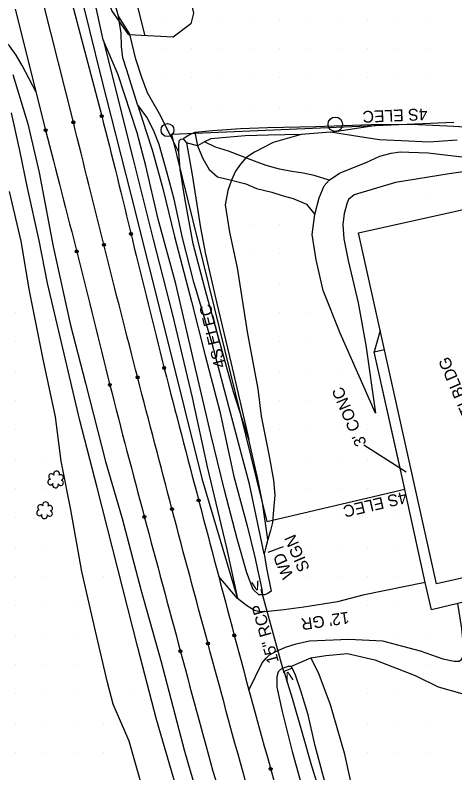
# Model space of a CAD drawing. Extents: x 1548934 to 1561348, y 809680 to 824075.
# Drawn here: x 1551639.7 to 1551789.7, y 811053 to 811311.4 of the extents above; entities that cross this region are included whole.
import ezdxf

# ---------------------------------------------------------------- set-up
doc = ezdxf.new("R2010")
doc.units = 0
for name, color, linetype in [('Default', 7, 'Continuous'), ('E_NCDOT_Vertical_Profile_Ground_Line', 7, 'Continuous'), ('Exist Building', 7, 'Continuous'), ('Exist Building Foundations Text', 7, 'Continuous'), ('Exist DTM QL2 LIDAR Elevation Point', 7, 'Continuous'), ('Exist Other Culture Area Outline', 7, 'Continuous'), ('Exist Other Culture Area Outline Leader', 7, 'Continuous'), ('Exist Other Culture Area Outline Text', 7, 'Continuous'), ('Exist Other Culture Fence Line Text', 7, 'Continuous'), ('Exist Other Culture Sign', 7, 'Continuous'), ('Exist Other Culture Sign Text', 7, 'Continuous'), ('Exist Roads Soil', 7, 'Continuous'), ('Exist Roads Soil Text', 7, 'Continuous'), ('Exist Structure Minor Culvert Topo', 7, 'Continuous'), ('Exist Structure Minor Culvert Topo Terminator', 7, 'Continuous'), ('Exist Structure Minor Pipes RCP 15 Inch Text', 7, 'Continuous'), ('Exist Utilities Other Pole CELL', 7, 'Continuous'), ('Exist Vegetation Shrub CELL', 7, 'Continuous'), ('Exist Vegetation Woods Line', 7, 'Continuous'), ('P_NCDOT_Horizontal_Alignment_Tick_Large', 7, 'Continuous'), ('P_NCDOT_Vertical_Profile_Grade_Minor_Road', 7, 'Continuous'), ('P_RDY_Dimension_Text', 7, 'Continuous'), ('P_RDY_Paved_Shoulder', 7, 'Continuous'), ('PH Exist DTM Breakline', 7, 'Continuous')]:
    doc.layers.add(name, color=color, linetype=linetype)

# ---------------------------------------------------------------- blocks, each defined once
blk = doc.blocks.new('SurveyPointCell')
at = {"layer": 'Default'}
for p, q in [((-0.5, 0), (0.5, 0)), ((0, -0.5), (0, 0.5))]:
    blk.add_line(p, q, dxfattribs=at)
blk.add_circle((0, 0), 0.5, dxfattribs=at)

msp = doc.modelspace()

# ---------------------------------------------------------------- linework, layer by layer
at = {"layer": 'E_NCDOT_Vertical_Profile_Ground_Line'}
for p, q in [((1551658.19, 811318.94), (1551669.23, 811277)), ((1551639.73, 811313.5), (1551650.09, 811272.18))]:
    msp.add_line(p, q, dxfattribs=at)
for points in [[(1551669.23, 811277), (1551672.74, 811263.65), (1551679.61, 811234.97), (1551690.37, 811191.22), (1551702.41, 811145.66), (1551714.33, 811100.03), (1551727, 811053.45), (1551740.47, 811006.5), (1551755.13, 810959.34), (1551769.1, 810915.85), (1551778.93, 810888.33), (1551783.17, 810876.09)], [(1551650.09, 811272.18), (1551653.54, 811258.38), (1551661.25, 811229.55), (1551671.78, 811185.41), (1551683.85, 811140.03), (1551696.07, 811094.56), (1551708.62, 811047.91), (1551722.36, 811000.57), (1551736.98, 810952.93), (1551751.55, 810908.96), (1551760.88, 810880.92), (1551765.29, 810868.44)]]:
    msp.add_open_spline(points, degree=3, dxfattribs=at)
at = {"layer": 'Exist Building'}
msp.add_lwpolyline([(1551783.41, 811117.5), (1551756.83, 811237.21), (1551806.41, 811248.22), (1551832.98, 811128.51)], close=True, dxfattribs=at)
at = {"layer": 'Exist DTM QL2 LIDAR Elevation Point'}
for p, q in [((1551689.99, 811310.04), (1551689.99, 811310.04)), ((1551699.99, 811310.04), (1551699.99, 811310.04)), ((1551710, 811310.04), (1551710, 811310.04)), ((1551720, 811310.04), (1551720, 811310.04)), ((1551730, 811310.04), (1551730, 811310.04)), ((1551740, 811310.04), (1551740, 811310.04)), ((1551750, 811310.04), (1551750, 811310.04)), ((1551760, 811310.04), (1551760, 811310.04)), ((1551770, 811310.04), (1551770, 811310.04)), ((1551780, 811310.04), (1551780, 811310.04)), ((1551689.99, 811300.03), (1551689.99, 811300.03)), ((1551699.99, 811300.03), (1551699.99, 811300.03)), ((1551710, 811300.03), (1551710, 811300.03)), ((1551720, 811300.03), (1551720, 811300.03)), ((1551730, 811300.03), (1551730, 811300.03)), ((1551740, 811300.03), (1551740, 811300.03)), ((1551750, 811300.03), (1551750, 811300.03)), ((1551760, 811300.03), (1551760, 811300.03)), ((1551770, 811300.03), (1551770, 811300.03)), ((1551780, 811300.03), (1551780, 811300.03)), ((1551689.99, 811290.03), (1551689.99, 811290.03)), ((1551699.99, 811290.03), (1551699.99, 811290.03)), ((1551710, 811290.03), (1551710, 811290.03)), ((1551720, 811290.03), (1551720, 811290.03)), ((1551730, 811290.03), (1551730, 811290.03)), ((1551740, 811290.03), (1551740, 811290.03)), ((1551750, 811290.03), (1551750, 811290.03)), ((1551760, 811290.03), (1551760, 811290.03)), ((1551770, 811290.03), (1551770, 811290.03)), ((1551780, 811290.03), (1551780, 811290.03)), ((1551699.99, 811280.03), (1551699.99, 811280.03)), ((1551710, 811280.03), (1551710, 811280.03)), ((1551720, 811280.03), (1551720, 811280.03)), ((1551730, 811280.03), (1551730, 811280.03)), ((1551740, 811280.03), (1551740, 811280.03)), ((1551750, 811280.03), (1551750, 811280.03)), ((1551760, 811280.03), (1551760, 811280.03)), ((1551770, 811280.03), (1551770, 811280.03)), ((1551780, 811280.03), (1551780, 811280.03)), ((1551780, 811250.03), (1551780, 811250.03)), ((1551720, 811240.03), (1551720, 811240.03)), ((1551730, 811240.03), (1551730, 811240.03)), ((1551760, 811240.03), (1551760, 811240.03)), ((1551720, 811230.03), (1551720, 811230.03)), ((1551730, 811230.03), (1551730, 811230.03)), ((1551730, 811220.03), (1551730, 811220.03)), ((1551639.99, 811210.03), (1551639.99, 811210.03)), ((1551730, 811210.03), (1551730, 811210.03)), ((1551740, 811210.03), (1551740, 811210.03)), ((1551639.99, 811200.03), (1551639.99, 811200.03)), ((1551730, 811200.03), (1551730, 811200.03)), ((1551740, 811200.03), (1551740, 811200.03)), ((1551639.99, 811190.03), (1551639.99, 811190.03)), ((1551730, 811190.03), (1551730, 811190.03)), ((1551740, 811190.03), (1551740, 811190.03)), ((1551750, 811190.03), (1551750, 811190.03)), ((1551639.99, 811180.03), (1551639.99, 811180.03)), ((1551730, 811180.03), (1551730, 811180.03)), ((1551740, 811180.03), (1551740, 811180.03)), ((1551750, 811180.03), (1551750, 811180.03)), ((1551639.99, 811170.02), (1551639.99, 811170.02)), ((1551730, 811170.02), (1551730, 811170.02)), ((1551740, 811170.02), (1551740, 811170.02)), ((1551750, 811170.02), (1551750, 811170.02)), ((1551760, 811170.02), (1551760, 811170.02)), ((1551639.99, 811160.02), (1551639.99, 811160.02)), ((1551649.99, 811160.02), (1551649.99, 811160.02)), ((1551740, 811160.02), (1551740, 811160.02)), ((1551750, 811160.02), (1551750, 811160.02)), ((1551760, 811160.02), (1551760, 811160.02)), ((1551639.99, 811150.02), (1551639.99, 811150.02)), ((1551649.99, 811150.02), (1551649.99, 811150.02)), ((1551740, 811150.02), (1551740, 811150.02)), ((1551750, 811150.02), (1551750, 811150.02)), ((1551760, 811150.02), (1551760, 811150.02)), ((1551639.99, 811140.02), (1551639.99, 811140.02)), ((1551649.99, 811140.02), (1551649.99, 811140.02)), ((1551740, 811140.02), (1551740, 811140.02)), ((1551750, 811140.02), (1551750, 811140.02)), ((1551760, 811140.02), (1551760, 811140.02)), ((1551770, 811140.02), (1551770, 811140.02)), ((1551639.99, 811130.02), (1551639.99, 811130.02)), ((1551649.99, 811130.02), (1551649.99, 811130.02)), ((1551740, 811130.02), (1551740, 811130.02)), ((1551750, 811130.02), (1551750, 811130.02)), ((1551760, 811130.02), (1551760, 811130.02)), ((1551770, 811130.02), (1551770, 811130.02)), ((1551639.99, 811120.02), (1551639.99, 811120.02)), ((1551649.99, 811120.02), (1551649.99, 811120.02)), ((1551669.99, 811120.02), (1551669.99, 811120.02)), ((1551740, 811120.02), (1551740, 811120.02)), ((1551750, 811120.02), (1551750, 811120.02)), ((1551760, 811120.02), (1551760, 811120.02)), ((1551770, 811120.02), (1551770, 811120.02)), ((1551639.99, 811110.02), (1551639.99, 811110.02)), ((1551649.99, 811110.02), (1551649.99, 811110.02)), ((1551659.99, 811110.02), (1551659.99, 811110.02)), ((1551760, 811110.02), (1551760, 811110.02)), ((1551770, 811110.02), (1551770, 811110.02)), ((1551639.99, 811100.02), (1551639.99, 811100.02)), ((1551649.99, 811100.02), (1551649.99, 811100.02)), ((1551659.99, 811100.02), (1551659.99, 811100.02)), ((1551720, 811100.02), (1551720, 811100.02)), ((1551730, 811100.02), (1551730, 811100.02)), ((1551770, 811100.02), (1551770, 811100.02)), ((1551780, 811100.02), (1551780, 811100.02)), ((1551639.99, 811090.02), (1551639.99, 811090.02)), ((1551649.99, 811090.02), (1551649.99, 811090.02)), ((1551659.99, 811090.02), (1551659.99, 811090.02)), ((1551780, 811090.02), (1551780, 811090.02)), ((1551639.99, 811080.02), (1551639.99, 811080.02)), ((1551649.99, 811080.02), (1551649.99, 811080.02)), ((1551659.99, 811080.02), (1551659.99, 811080.02)), ((1551679.99, 811080.02), (1551679.99, 811080.02)), ((1551760, 811080.02), (1551760, 811080.02)), ((1551770, 811080.02), (1551770, 811080.02)), ((1551639.99, 811070.02), (1551639.99, 811070.02)), ((1551649.99, 811070.02), (1551649.99, 811070.02)), ((1551659.99, 811070.02), (1551659.99, 811070.02)), ((1551669.99, 811070.02), (1551669.99, 811070.02)), ((1551760, 811070.02), (1551760, 811070.02)), ((1551770, 811070.02), (1551770, 811070.02)), ((1551780, 811070.02), (1551780, 811070.02)), ((1551639.99, 811060.02), (1551639.99, 811060.02)), ((1551649.99, 811060.02), (1551649.99, 811060.02)), ((1551659.99, 811060.02), (1551659.99, 811060.02)), ((1551669.99, 811060.02), (1551669.99, 811060.02)), ((1551760, 811060.02), (1551760, 811060.02)), ((1551770, 811060.02), (1551770, 811060.02)), ((1551780, 811060.02), (1551780, 811060.02))]:
    msp.add_line(p, q, dxfattribs=at)
at = {"layer": 'Exist Other Culture Area Outline'}
msp.add_lwpolyline([(1551799.11, 811112.91), (1551790.77, 811110.81), (1551781.78, 811108.69), (1551779.56, 811117.98), (1551770.71, 811158.5), (1551762.17, 811196.63), (1551765.67, 811197.39)], dxfattribs=at)
at = {"layer": 'Exist Other Culture Area Outline Leader'}
msp.add_line((1551773.12, 811155.54), (1551758.67, 811164.84), dxfattribs=at)
at = {"layer": 'Exist Other Culture Sign'}
msp.add_line((1551725.99, 811128.26), (1551731.2, 811130.22), dxfattribs=at)
at = {"layer": 'Exist Roads Soil'}
for points in [[(1551779.56, 811117.98), (1551758.34, 811113.65), (1551749.64, 811111.35), (1551738.13, 811109.5), (1551731.41, 811108.67), (1551728.21, 811108.3), (1551725.15, 811107.99), (1551722.72, 811108.01), (1551721.38, 811108.45), (1551718.61, 811110.1), (1551715.6, 811112.46), (1551709.14, 811119.96)], [(1551719.47, 811081.25), (1551723.96, 811090.53), (1551725.4, 811092.26), (1551726.5, 811093.32), (1551728.63, 811094.38), (1551731.91, 811095.85), (1551735.51, 811097.03), (1551740.14, 811098.04), (1551753.48, 811098.66), (1551765.04, 811098.05), (1551777.83, 811094.69), (1551785.62, 811091.88), (1551789.5, 811091.12), (1551791.17, 811091.18), (1551791.89, 811091.54), (1551792.56, 811092.56), (1551792.81, 811095.13), (1551792.06, 811102.27), (1551790.77, 811110.81)]]:
    msp.add_lwpolyline(points, dxfattribs=at)
at = {"layer": 'Exist Structure Minor Culvert Topo'}
msp.add_line((1551723.53, 811115.64), (1551731.34, 811087.11), dxfattribs=at)
at = {"layer": 'Exist Utilities Other Pole CELL'}
msp.add_circle((1551748.9, 811274.23), 2.46, dxfattribs=at)
at = {"layer": 'Exist Vegetation Shrub CELL'}
for p, q in [((1551653.59, 811152.91), (1551653.59, 811152.91)), ((1551649.83, 811142.4), (1551649.83, 811142.4))]:
    msp.add_line(p, q, dxfattribs=at)
for centre, radius, start, end in [((1551652.11, 811154.04), 0.968, 35.8908, 245.4216), ((1551653.82, 811154.95), 0.99, 334.8391, 200.4717), ((1551655.26, 811153.78), 0.929, 284.4567, 126.0861), ((1551651.79, 811152.21), 0.955, 95.1099, 327.9534), ((1551653.46, 811151.23), 0.984, 151.2797, 21.387), ((1551655.22, 811151.98), 0.937, 204.9913, 73.4601), ((1551648.35, 811143.53), 0.968, 35.8908, 245.4216), ((1551650.06, 811144.45), 0.99, 334.8391, 200.4717), ((1551651.5, 811143.27), 0.929, 284.4567, 126.0861), ((1551648.03, 811141.7), 0.955, 95.1099, 327.9534), ((1551649.7, 811140.72), 0.984, 151.2797, 21.387), ((1551651.47, 811141.48), 0.937, 204.9913, 73.4601)]:
    msp.add_arc(centre, radius, start, end, dxfattribs=at)
at = {"layer": 'Exist Vegetation Woods Line'}
msp.add_lwpolyline([(1551571.72, 811842.18), (1551613.6, 811680.5), (1551674.88, 811449.43), (1551691.44, 811358.19), (1551695.57, 811334.77), (1551700.55, 811312.09), (1551699.58, 811308.43), (1551693.58, 811303.93), (1551678.43, 811304.73), (1551672.72, 811312.99), (1551668.24, 811325.43), (1551622.53, 811506.2), (1551580.25, 811682.82), (1551545.51, 811843.36)], dxfattribs=at)
at = {"layer": 'P_NCDOT_Horizontal_Alignment_Tick_Large'}
for radius in [2.2, 0.0707]:
    msp.add_circle((1551691.66, 811272.25), radius, dxfattribs=at)
at = {"layer": 'P_NCDOT_Vertical_Profile_Grade_Minor_Road'}
msp.add_line((1551659.56, 811274.89), (1551649.24, 811315.83), dxfattribs=at)
msp.add_open_spline([(1551774.27, 810871.88), (1551769.96, 810884.28), (1551760.75, 810912.23), (1551745.66, 810955.91), (1551731.5, 811003.54), (1551718, 811050.78), (1551705.43, 811097.26), (1551693.24, 811142.66), (1551681.43, 811187.98), (1551670.2, 811231.95), (1551663.06, 811260.98), (1551659.56, 811274.89)], degree=3, dxfattribs=at)
at = {"layer": 'P_RDY_Dimension_Text'}
for p, q in [((1551693.09, 811270.85), (1551789.4, 811274.96)), ((1551693.09, 811270.85), (1551725.58, 811138.72)), ((1551764.22, 811203.9), (1551762.17, 811196.63)), ((1551772.63, 811149.74), (1551762.17, 811196.63)), ((1551725.58, 811138.72), (1551772.63, 811149.74))]:
    msp.add_line(p, q, dxfattribs=at)
msp.add_lwpolyline([(1551684.08, 811304.43), (1551679.28, 811323.48), (1551668.38, 811365.77)], dxfattribs=at)
at = {"layer": 'P_RDY_Paved_Shoulder'}
msp.add_lwpolyline([(1551646.82, 811285.2), (1551642.05, 811294.29), (1551640.08, 811297.74), (1551637.72, 811301), (1551636.21, 811302.45), (1551634.3, 811304.06), (1551631.77, 811305.85), (1551630.16, 811306.76), (1551627.75, 811307.35), (1551623.68, 811308.05), (1551617.73, 811308.27), (1551596.5, 811302.97), (1551582.23, 811299.78), (1551565.18, 811295.98), (1551551.83, 811293.21), (1551545.59, 811292.49), (1551536.15, 811291.34), (1551516.8, 811289.63), (1551498.66, 811288.84), (1551485.69, 811288.46), (1551472.69, 811288.31), (1551452.39, 811288.24), (1551432.36, 811287.99)], dxfattribs=at)
at = {"layer": 'PH Exist DTM Breakline'}
for points in [[(1551534.96, 811833.74), (1551549.41, 811779.1), (1551560.58, 811733.74), (1551572.57, 811684.16), (1551581.33, 811646.33), (1551598.34, 811576.19), (1551608.87, 811531.03), (1551621.47, 811482.36), (1551627.81, 811455.82), (1551633.18, 811432.34), (1551647.15, 811378.38), (1551657.12, 811338.6), (1551669.09, 811290.08), (1551679.12, 811250.32), (1551691.58, 811200.98), (1551703.42, 811153.47), (1551715.6, 811112.46)], [(1551669.67, 811303.01), (1551663.46, 811331.84), (1551653.59, 811372.99), (1551648.84, 811392.4), (1551636.09, 811443.6), (1551626.8, 811481.01), (1551614.05, 811530.5), (1551603.71, 811574.11), (1551596.24, 811605.78), (1551582.53, 811665.38), (1551576.53, 811692.42), (1551569, 811727.51), (1551561.82, 811755.9), (1551554.82, 811782.6), (1551545.34, 811820.46), (1551541.31, 811835.52)], [(1551681.45, 811280.95), (1551677.78, 811292.7), (1551676.4, 811296.94), (1551675.94, 811300.73), (1551675.86, 811305.27), (1551675, 811311.1), (1551670.08, 811328.33), (1551656.65, 811382.55), (1551654.14, 811393.37), (1551639.83, 811449.32), (1551631.58, 811483.28), (1551629.75, 811490.89)], [(1551695.52, 811264.73), (1551692.53, 811270.59), (1551688.9, 811277.76), (1551684.86, 811284.91), (1551682.89, 811290.14), (1551680.87, 811296.38), (1551678.8, 811304.95), (1551675, 811311.1)], [(1551790.45, 811268.75), (1551780.94, 811268.16), (1551771.51, 811268.59), (1551763.99, 811268.97), (1551757.31, 811269.99), (1551747.3, 811271.49), (1551737.29, 811270.73), (1551727.73, 811268.02), (1551721.34, 811264.71), (1551718.41, 811262.79), (1551716.53, 811260.67), (1551714.85, 811258.19), (1551713.49, 811255.19), (1551712.23, 811251.67), (1551711.39, 811246.74), (1551712.81, 811237.45), (1551715.41, 811225.32), (1551718.99, 811202.77), (1551722.53, 811184), (1551723.62, 811174.67), (1551726.4, 811160.99), (1551727.86, 811152.83), (1551728.26, 811147.77), (1551727.79, 811142.75), (1551727.45, 811138.41), (1551726.84, 811135.67), (1551725.86, 811132.59), (1551725.2, 811129.98), (1551724.69, 811127.76), (1551725.47, 811122.82), (1551727.03, 811114.98), (1551725.9, 811114.18), (1551724.79, 811113.72), (1551724.09, 811113.7), (1551722.87, 811113.77), (1551720.86, 811115.54), (1551718.71, 811121.21), (1551715.43, 811132.82), (1551711.15, 811149.44), (1551706.43, 811168.57), (1551701.21, 811190.98), (1551694.5, 811219.85), (1551688.49, 811241.92), (1551684.25, 811260.03), (1551681.36, 811271.35), (1551674.82, 811291.06), (1551669.67, 811303.01), (1551679.83, 811262.66), (1551686.8, 811234.94), (1551693.34, 811209.25), (1551700.1, 811181.1), (1551705.17, 811157.45), (1551711.84, 811129.76), (1551715.6, 811112.46)], [(1551638.94, 811291.18), (1551643.98, 811274.41), (1551647.9, 811257.81), (1551652.7, 811232.51), (1551658.43, 811206.12), (1551663.73, 811185.92), (1551670.47, 811159.24), (1551676.23, 811139.76), (1551682.62, 811115.57), (1551689.53, 811090.85), (1551697.49, 811060.44), (1551705.26, 811033.84)], [(1551724.69, 811127.76), (1551721.9, 811140.66), (1551719.66, 811151.5), (1551715.97, 811165.15), (1551711.08, 811183.53), (1551706.95, 811199.49), (1551700.64, 811220.4), (1551696.81, 811235.48), (1551693.96, 811248.72), (1551691.56, 811257.6), (1551688.87, 811267.31), (1551686.89, 811272.26), (1551684.66, 811276.7), (1551681.45, 811280.95), (1551684.37, 811271.81), (1551686.46, 811265.5), (1551690.04, 811252.37), (1551694.03, 811236.01), (1551699.89, 811213.75), (1551704.56, 811195.37), (1551709.56, 811176.26), (1551714.35, 811154.05), (1551718.89, 811137.31), (1551721.5, 811126.6), (1551723.73, 811116.18), (1551724.09, 811113.7)], [(1551625.86, 810940.3), (1551653.05, 810961.36), (1551669.7, 810973.54), (1551680.77, 810980.85), (1551695.07, 810990.25), (1551703.46, 810996.36), (1551705.28, 810997.82), (1551706.41, 810998.42), (1551708.74, 810999.85), (1551703.45, 811016.33), (1551699.21, 811031.98), (1551693.84, 811050.96), (1551687.88, 811071.22), (1551681.52, 811095.77), (1551674.77, 811122.66), (1551667.66, 811150.4), (1551661.81, 811173.23), (1551655.99, 811197.83), (1551650.7, 811220.08), (1551647.84, 811234.57), (1551643.86, 811252.56), (1551641.25, 811265.31), (1551638.41, 811278.13)], [(1551764.33, 811274.15), (1551742.13, 811273.31), (1551725.78, 811272.99), (1551716.63, 811272.62), (1551707.08, 811272.02), (1551700.95, 811271.45), (1551699.46, 811270.76), (1551697.06, 811269.27)], [(1551747.3, 811271.49), (1551764.33, 811274.15), (1551774.85, 811274.24), (1551787.12, 811273.73), (1551799.76, 811272.99), (1551811.5, 811273.85), (1551823, 811274.34), (1551838.34, 811274.74), (1551848.51, 811274.21)], [(1551737.29, 811270.73), (1551726.15, 811270.5), (1551718.12, 811270.27), (1551712.98, 811269.86), (1551706.5, 811269.25), (1551704.27, 811268.24), (1551701.93, 811266.83), (1551698.14, 811267.95)], [(1551700.95, 811271.45), (1551701.93, 811266.83), (1551703.71, 811262.54), (1551705.89, 811258.83), (1551708.78, 811256.32), (1551713.49, 811255.19), (1551718.35, 811253.91), (1551722.02, 811252.34), (1551727.23, 811251.12), (1551731.1, 811249.86), (1551734.51, 811248.88), (1551739.08, 811246.96), (1551741.91, 811243.47)], [(1551725.86, 811132.59), (1551724.07, 811145.21), (1551722.51, 811153.25), (1551719.39, 811166.68), (1551714.16, 811182.97), (1551709.08, 811201.49), (1551704.88, 811216.65), (1551700.38, 811233.47), (1551697.6, 811248.98), (1551695.97, 811258.9), (1551695.52, 811264.73), (1551695.52, 811266.98), (1551695.68, 811268.58), (1551696.26, 811269.13), (1551697.06, 811269.27), (1551698.14, 811267.95), (1551700.09, 811256.94), (1551702.97, 811238.86), (1551704.62, 811229.93), (1551708.48, 811213.1), (1551713.39, 811192.62), (1551719.39, 811166.68)], [(1551746.85, 811255.15), (1551741.76, 811256.73), (1551737.99, 811257.52), (1551734.14, 811258.13), (1551729.89, 811258.89), (1551725.32, 811260.21), (1551721.39, 811261.63), (1551718.41, 811262.79), (1551712.53, 811265.08), (1551708, 811266.47), (1551704.27, 811268.24)], [(1551796.38, 811258.61), (1551787.74, 811257.34), (1551769.41, 811254.37), (1551755.3, 811250.17), (1551753.38, 811248.6), (1551753.01, 811247.42), (1551751.99, 811243.83), (1551751.51, 811240.08), (1551751.79, 811235.18), (1551753.26, 811227.8), (1551756.66, 811213.35), (1551759.34, 811198.93), (1551762.65, 811175.72), (1551750.58, 811202.96), (1551744.8, 811217.59), (1551742.37, 811227.94), (1551741.08, 811236.65), (1551741.91, 811243.47), (1551743.36, 811249.1), (1551745.11, 811253.22), (1551746.85, 811255.15), (1551750.32, 811257.54), (1551759.63, 811261.36), (1551764.1, 811263.31), (1551767.96, 811264.35), (1551771.03, 811264.84), (1551773.96, 811264.72), (1551780.63, 811264.54), (1551789.25, 811263.41), (1551799.7, 811262.28)], [(1551683.15, 811047.86), (1551678.6, 811063.82), (1551673.15, 811076.45), (1551671.17, 811083.86), (1551667.07, 811101.38), (1551662.49, 811121.76), (1551658.67, 811142.75), (1551655.4, 811159.29), (1551653.51, 811174.47), (1551649.25, 811194.11), (1551644.57, 811217.42), (1551641.78, 811234.4), (1551637.75, 811251.31)], [(1551733.7, 811089.34), (1551740.58, 811092.26), (1551745.65, 811093.08), (1551753.09, 811093.73), (1551762.35, 811091.55), (1551776.2, 811086.24), (1551784.06, 811082.39), (1551792.04, 811080.05)], [(1551740.58, 811092.26), (1551743.29, 811086.68), (1551747.2, 811076.34), (1551751.97, 811059.91), (1551756, 811041.33), (1551761.97, 811016.35), (1551766.27, 811000.56), (1551772.99, 810977.55), (1551778.52, 810957.45), (1551784.14, 810939.23), (1551787.8, 810928.56), (1551788.72, 810921.41)], [(1551743.97, 811045.5), (1551740.88, 811055.34), (1551737.82, 811066.14), (1551734.32, 811078.34), (1551732.75, 811083.46), (1551731.42, 811087.74), (1551733.55, 811088.47), (1551734.18, 811088.87), (1551733.7, 811089.34), (1551732.88, 811089.33), (1551731.08, 811088.76), (1551730.21, 811088.24), (1551729.42, 811087.47), (1551728.93, 811085.84), (1551728.96, 811082.29), (1551730.81, 811073.95), (1551734.17, 811060.29), (1551739.78, 811040.33)], [(1551746.11, 811047.01), (1551742.09, 811062.23), (1551739.61, 811072.77), (1551737.19, 811081.06), (1551735.37, 811086.36), (1551734.18, 811088.87)]]:
    msp.add_lwpolyline(points, dxfattribs=at)

# ---------------------------------------------------------------- block references
at = {"layer": 'Default'}
for p in [(1551659.56, 811274.89), (1551669.23, 811277), (1551650.09, 811272.18), (1551679.2, 811236.82), (1551660.71, 811230.87), (1551669.97, 811233.13), (1551690.54, 811191.11), (1551681.49, 811187.93), (1551672, 811185.35), (1551702.31, 811145.96), (1551693.21, 811143), (1551683.8, 811140.31), (1551714.44, 811099.93), (1551705.47, 811097.19), (1551696.08, 811094.54), (1551726.86, 811054.37)]:
    msp.add_blockref('SurveyPointCell', p, dxfattribs=at)

# ---------------------------------------------------------------- texts
at = {"layer": 'Exist Building Foundations Text'}
msp.add_text('1SMTLBLDG', height=4.02, rotation=113.1852, dxfattribs=at).set_placement((1551800.19, 811165.93))
at = {"layer": 'Exist Other Culture Area Outline Text'}
msp.add_text("3' CONC", height=4.02, rotation=113.1417, dxfattribs=at).set_placement((1551759.69, 811165.42))
at = {"layer": 'Exist Other Culture Fence Line Text'}
for rotation, p in [(182.4464, (1551780.24, 811279.68)), (103.8156, (1551711.63, 811191.66)), (193.1841, (1551772.8, 811149.03))]:
    msp.add_text('4S ELEC', height=4.02, rotation=rotation, dxfattribs=at).set_placement(p)
at = {"layer": 'Exist Other Culture Sign Text'}
for s, p in [('SIGN', (1551740.28, 811122.66)), ('WD', (1551734.74, 811120.27))]:
    msp.add_text(s, height=4.02, rotation=113.3282, dxfattribs=at).set_placement(p)
at = {"layer": 'Exist Roads Soil Text'}
msp.add_text("12' GR", height=4.02, rotation=188.2961, dxfattribs=at).set_placement((1551753.38, 811108.03))
at = {"layer": 'Exist Structure Minor Culvert Topo Terminator'}
for rotation, p in [(15.3075, (1551720.98, 811114.95)), (195.3075, (1551733.89, 811087.81))]:
    msp.add_text('v', height=4, rotation=rotation, dxfattribs=at).set_placement(p)
at = {"layer": 'Exist Structure Minor Pipes RCP 15 Inch Text'}
msp.add_text('15" RCP', height=4.02, rotation=105.4201, dxfattribs=at).set_placement((1551729.7, 811090.97))

doc.saveas('drawing.dxf')
